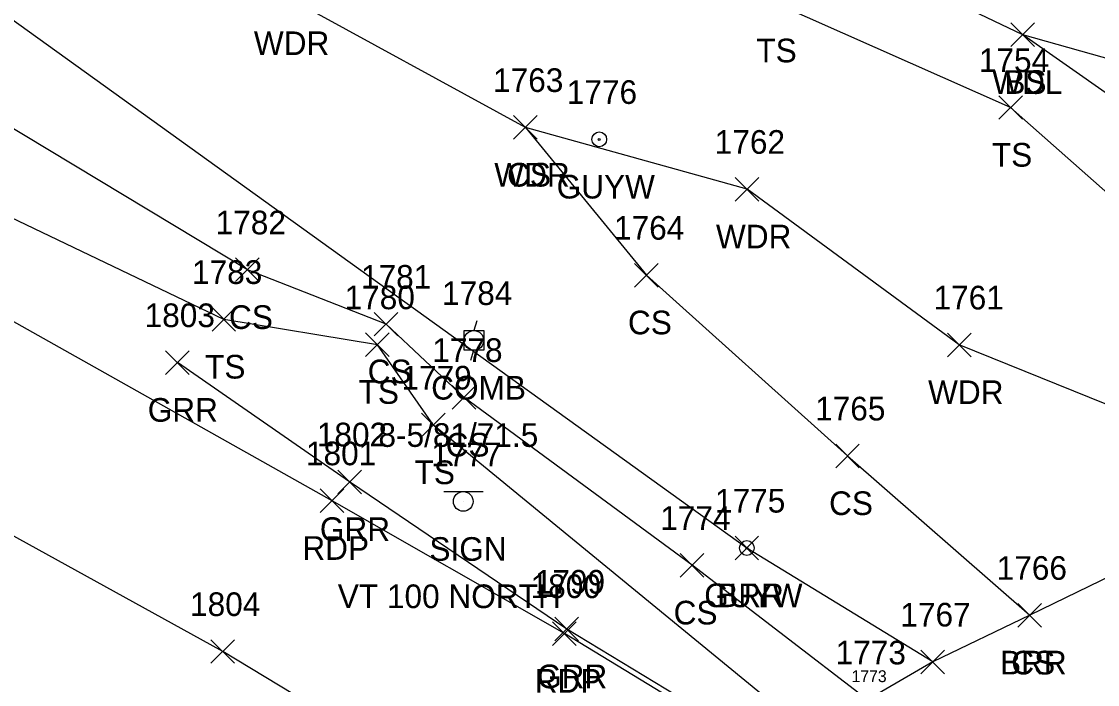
# Model space of a CAD drawing. Extents: x 1537342 to 1542195, y 163002 to 168596.
# Drawn here: x 1541736 to 1541827.1, y 163353.6 to 163409.7 of the extents above; entities that cross this region are included whole.
import ezdxf

# ---------------------------------------------------------------- set-up
doc = ezdxf.new("R2010")
doc.units = 0
for name, color, linetype in [('B_I', 7, 'Continuous'), ('L_A', 7, 'Continuous'), ('L_I', 7, 'Continuous'), ('L_TIC', 7, 'Continuous'), ('LABL', 7, 'Continuous'), ('LAWA', 7, 'Continuous'), ('LELB', 7, 'Continuous'), ('P_A', 7, 'Continuous'), ('P_I', 7, 'Continuous'), ('P_TIC', 7, 'Continuous'), ('PET', 7, 'Continuous'), ('PRC', 7, 'Continuous'), ('R_A', 7, 'Continuous'), ('R_I', 7, 'Continuous'), ('R_TIC', 7, 'Continuous'), ('RGR', 7, 'Continuous'), ('S_A', 7, 'Continuous'), ('S_C', 7, 'Continuous'), ('S_I', 7, 'Continuous'), ('SSGN', 7, 'Continuous'), ('U_A', 7, 'Continuous'), ('U_C', 7, 'Continuous'), ('U_I', 7, 'Continuous'), ('UP', 7, 'Continuous'), ('UPGW', 7, 'Continuous')]:
    doc.layers.add(name, color=color, linetype=linetype)

msp = doc.modelspace()

# ---------------------------------------------------------------- linework, layer by layer
at = {"layer": 'L_TIC'}
for points in [[(1541819.736, 163407.535), (1541821.736, 163409.535)], [(1541821.736, 163407.535), (1541819.736, 163409.535)], [(1541819.736, 163407.535), (1541821.736, 163409.535)], [(1541821.736, 163407.535), (1541819.736, 163409.535)], [(1541818.716, 163401.383), (1541820.716, 163403.383)], [(1541820.716, 163401.383), (1541818.716, 163403.383)], [(1541777.643, 163399.697), (1541779.643, 163401.697)], [(1541779.643, 163399.697), (1541777.643, 163401.697)], [(1541777.643, 163399.697), (1541779.643, 163401.697)], [(1541779.643, 163399.697), (1541777.643, 163401.697)], [(1541796.408, 163394.469), (1541798.408, 163396.469)], [(1541798.408, 163394.469), (1541796.408, 163396.469)], [(1541754.111, 163387.656), (1541756.111, 163389.656)], [(1541756.111, 163387.656), (1541754.111, 163389.656)], [(1541787.881, 163387.202), (1541789.881, 163389.202)], [(1541789.881, 163387.202), (1541787.881, 163389.202)], [(1541752.114, 163383.462), (1541754.114, 163385.462)], [(1541754.114, 163383.462), (1541752.114, 163385.462)], [(1541765.848, 163383.06), (1541767.848, 163385.06)], [(1541767.848, 163383.06), (1541765.848, 163385.06)], [(1541765.113, 163381.325), (1541767.113, 163383.325)], [(1541767.113, 163381.325), (1541765.113, 163383.325)], [(1541814.363, 163381.307), (1541816.363, 163383.307)], [(1541816.363, 163381.307), (1541814.363, 163383.307)], [(1541772.45, 163376.865), (1541774.45, 163378.865)], [(1541774.45, 163376.865), (1541772.45, 163378.865)], [(1541769.849, 163374.533), (1541771.849, 163376.533)], [(1541771.849, 163374.533), (1541769.849, 163376.533)], [(1541804.905, 163371.92), (1541806.905, 163373.92)], [(1541806.905, 163371.92), (1541804.905, 163373.92)], [(1541796.385, 163364.127), (1541798.385, 163366.127)], [(1541798.385, 163364.127), (1541796.385, 163366.127)], [(1541791.746, 163362.667), (1541793.746, 163364.667)], [(1541793.746, 163362.667), (1541791.746, 163364.667)], [(1541820.327, 163358.44), (1541822.327, 163360.44)], [(1541822.327, 163358.44), (1541820.327, 163360.44)], [(1541820.327, 163358.44), (1541822.327, 163360.44)], [(1541822.327, 163358.44), (1541820.327, 163360.44)], [(1541812.12, 163354.493), (1541814.12, 163356.493)], [(1541814.12, 163354.493), (1541812.12, 163356.493)], [(1541812.12, 163354.493), (1541814.12, 163356.493)], [(1541814.12, 163354.493), (1541812.12, 163356.493)]]:
    msp.add_lwpolyline(points, dxfattribs=at)
at = {"layer": 'LABL'}
msp.add_lwpolyline([(1541844.344, 163370.601), (1541821.327, 163359.44), (1541813.12, 163355.493), (1541797.385, 163365.127), (1541723.782, 163418.037)], dxfattribs=at)
at = {"layer": 'LAWA'}
for points in [[(1541858.304, 163366.25), (1541851.228, 163367.969), (1541844.344, 163370.601), (1541815.363, 163382.307), (1541797.408, 163395.469), (1541778.643, 163400.697), (1541758.293, 163411.817), (1541723.782, 163418.037), (1541697.041, 163431.454), (1541651.959, 163468.668), (1541626.155, 163491.842), (1541623.989, 163498.515), (1541617.661, 163502.857), (1541594.181, 163514.443)], [(1541858.304, 163366.25), (1541879.508, 163370.149), (1541893.624, 163370.513), (1541908.1, 163373.664), (1541889.776, 163380.927), (1541869.01, 163392.194), (1541846.903, 163401.174), (1541820.736, 163408.535), (1541800.161, 163418.359), (1541771.307, 163422.691), (1541733.429, 163438.827), (1541707.979, 163450.898), (1541667.545, 163486.779), (1541634.882, 163501.174)]]:
    msp.add_lwpolyline(points, dxfattribs=at)
at = {"layer": 'LELB'}
for points in [[(1541813.12, 163355.493), (1541807.593, 163352.289), (1541792.746, 163363.667), (1541773.45, 163377.865), (1541766.848, 163384.06), (1541755.111, 163388.656), (1541717.311, 163411.392), (1541693.125, 163425.745), (1541646.546, 163461.211), (1541615.06, 163486.328), (1541589.07, 163507.087)], [(1541806.46, 163346.352), (1541770.849, 163375.533), (1541766.113, 163382.325), (1541753.114, 163384.462), (1541712.964, 163403.647), (1541689.279, 163419.489), (1541645.558, 163455.193), (1541611.137, 163481.599), (1541585.037, 163504.654)], [(1541844.344, 163370.601), (1541854.929, 163375.483), (1541838.125, 163386.11), (1541819.716, 163402.383), (1541799.781, 163411.203), (1541771.307, 163422.691)], [(1541851.228, 163367.969), (1541863.142, 163374.68), (1541842.598, 163393.255), (1541820.736, 163408.535)], [(1541778.643, 163400.697), (1541788.881, 163388.202), (1541805.905, 163372.92), (1541821.327, 163359.44)]]:
    msp.add_lwpolyline(points, dxfattribs=at)
at = {"layer": 'P_TIC'}
for points in [[(1541761.271, 163368.13), (1541763.271, 163370.13)], [(1541763.271, 163368.13), (1541761.271, 163370.13)], [(1541780.937, 163356.897), (1541782.937, 163358.897)], [(1541782.937, 163356.897), (1541780.937, 163358.897)], [(1541752.026, 163355.379), (1541754.026, 163357.379)], [(1541754.026, 163355.379), (1541752.026, 163357.379)]]:
    msp.add_lwpolyline(points, dxfattribs=at)
at = {"layer": 'PET'}
msp.add_lwpolyline([(1541804.882, 163343.94), (1541781.937, 163357.897), (1541762.271, 163369.13), (1541719.068, 163393.382), (1541702.013, 163402.189), (1541685.469, 163410.812), (1541633.416, 163436.219), (1541598.663, 163451.943), (1541573.75, 163461.19), (1541557.97, 163467.971)], dxfattribs=at)
at = {"layer": 'PRC'}
msp.add_lwpolyline([(1541786.304, 163336.277), (1541753.026, 163356.379), (1541711.826, 163379.06), (1541677.625, 163397.186), (1541623.384, 163422.529), (1541592.115, 163436.736), (1541548.189, 163454.577)], dxfattribs=at)
at = {"layer": 'R_TIC'}
for points in [[(1541748.181, 163379.81), (1541750.181, 163381.81)], [(1541750.181, 163379.81), (1541748.181, 163381.81)], [(1541762.753, 163369.726), (1541764.753, 163371.726)], [(1541764.753, 163369.726), (1541762.753, 163371.726)], [(1541781.138, 163357.273), (1541783.138, 163359.273)], [(1541783.138, 163357.273), (1541781.138, 163359.273)]]:
    msp.add_lwpolyline(points, dxfattribs=at)
at = {"layer": 'RGR'}
msp.add_lwpolyline([(1541805.439, 163344.183), (1541782.138, 163358.273), (1541763.753, 163370.726), (1541749.181, 163380.81)], dxfattribs=at)
at = {"layer": 'SSGN'}
for p, q in [((1541771.731, 163369.901), (1541775.064, 163369.901)), ((1541773.378, 163369.068), (1541773.378, 163369.068))]:
    msp.add_line(p, q, dxfattribs=at)
msp.add_circle((1541773.378, 163369.068), 0.833, dxfattribs=at)
at = {"layer": 'UP'}
for p, q in [((1541774.528, 163384.35), (1541774.278, 163383.517)), ((1541773.445, 163381.85), (1541773.445, 163383.517)), ((1541773.445, 163383.517), (1541775.112, 163383.517)), ((1541775.112, 163383.517), (1541775.112, 163381.85)), ((1541774.278, 163382.683), (1541774.278, 163382.683)), ((1541775.112, 163381.85), (1541773.445, 163381.85)), ((1541774.028, 163381.017), (1541774.278, 163381.85))]:
    msp.add_line(p, q, dxfattribs=at)
msp.add_circle((1541774.278, 163382.683), 0.833, dxfattribs=at)
at = {"layer": 'UPGW'}
for centre, radius in [((1541784.89, 163399.686), 0.625), ((1541784.89, 163399.686), 0.0833), ((1541797.385, 163365.127), 0.625), ((1541797.385, 163365.127), 0.0833)]:
    msp.add_circle(centre, radius, dxfattribs=at)

# ---------------------------------------------------------------- texts
at = {"layer": 'B_I'}
msp.add_text('1773', height=1, dxfattribs=at).set_placement((1541806.247, 163353.789))
msp.add_text('1773', height=1, dxfattribs=at).set_placement((1541806.247, 163353.789))
at = {"layer": 'L_A'}
for s, p in [('WDR', (1541755.655, 163406.817)), ('TS', (1541798.191, 163406.203)), ('WDL', (1541818.154, 163403.535)), ('BS', (1541819.177, 163403.535)), ('TS', (1541818.126, 163397.383)), ('WDR', (1541776.005, 163395.697)), ('CS', (1541777.084, 163395.697)), ('WDR', (1541794.77, 163390.469)), ('CS', (1541753.552, 163383.656)), ('CS', (1541787.322, 163383.202)), ('TS', (1541751.524, 163379.462)), ('CS', (1541765.289, 163379.06)), ('TS', (1541764.522, 163377.325)), ('WDR', (1541812.725, 163377.307)), ('CS', (1541771.891, 163372.865)), ('TS', (1541769.259, 163370.533)), ('CS', (1541804.346, 163367.92)), ('BRR', (1541794.873, 163360.127)), ('CS', (1541791.187, 163358.667)), ('BRR', (1541818.815, 163354.44)), ('CS', (1541819.768, 163354.44))]:
    msp.add_text(s, height=2, dxfattribs=at).set_placement(p)
at = {"layer": 'L_I'}
for s, p in [('1754', (1541817.024, 163405.383)), ('1763', (1541775.903, 163403.697)), ('1763', (1541775.903, 163403.697)), ('1762', (1541794.668, 163398.469)), ('1782', (1541752.418, 163391.656)), ('1764', (1541786.141, 163391.202)), ('1783', (1541750.421, 163387.462)), ('1781', (1541764.722, 163387.06)), ('1780', (1541763.334, 163385.325)), ('1761', (1541813.19, 163385.307)), ('1778', (1541770.758, 163380.865)), ('1779', (1541768.149, 163378.533)), ('1765', (1541803.165, 163375.92)), ('1775', (1541794.692, 163368.127)), ('1774', (1541790.054, 163366.667)), ('1766', (1541818.532, 163362.44)), ('1766', (1541818.532, 163362.44)), ('1767', (1541810.38, 163358.493)), ('1767', (1541810.38, 163358.493)), ('1773', (1541804.901, 163355.289))]:
    msp.add_text(s, height=2, dxfattribs=at).set_placement(p)
at = {"layer": 'P_A'}
for p in [(1541759.759, 163364.13), (1541779.425, 163352.897)]:
    msp.add_text('RDP', height=2, dxfattribs=at).set_placement(p)
at = {"layer": 'P_I'}
for s, p in [('1801', (1541760.066, 163372.13)), ('1800', (1541779.079, 163360.897)), ('1804', (1541750.255, 163359.379))]:
    msp.add_text(s, height=2, dxfattribs=at).set_placement(p)
at = {"layer": 'R_A'}
for p in [(1541746.67, 163375.81), (1541761.241, 163365.726), (1541779.626, 163353.273)]:
    msp.add_text('GRR', height=2, dxfattribs=at).set_placement(p)
at = {"layer": 'R_I'}
for s, p in [('1803', (1541746.41, 163383.81)), ('1802', (1541760.982, 163373.726)), ('1799', (1541779.437, 163361.273))]:
    msp.add_text(s, height=2, dxfattribs=at).set_placement(p)
at = {"layer": 'S_A'}
msp.add_text('SIGN', height=2, dxfattribs=at).set_placement((1541770.516, 163364.048))
at = {"layer": 'S_C'}
msp.add_text('VT 100 NORTH', height=2, dxfattribs=at).set_placement((1541762.76, 163360.048))
at = {"layer": 'S_I'}
msp.add_text('1777', height=2, dxfattribs=at).set_placement((1541770.666, 163372.048))
at = {"layer": 'U_A'}
for s, p in [('GUYW', (1541781.284, 163394.686)), ('COMB', (1541770.664, 163377.683)), ('GUYW', (1541793.778, 163360.127))]:
    msp.add_text(s, height=2, dxfattribs=at).set_placement(p)
at = {"layer": 'U_C'}
msp.add_text('8-5/81/71.5', height=2, dxfattribs=at).set_placement((1541766.2, 163373.683))
at = {"layer": 'U_I'}
for s, p in [('1776', (1541782.142, 163402.686)), ('1784', (1541771.586, 163385.683)), ('1775', (1541794.692, 163368.127))]:
    msp.add_text(s, height=2, dxfattribs=at).set_placement(p)

doc.saveas('drawing.dxf')
